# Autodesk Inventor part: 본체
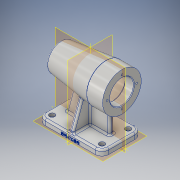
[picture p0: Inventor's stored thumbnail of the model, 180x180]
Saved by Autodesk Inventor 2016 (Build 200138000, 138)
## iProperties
Created: 2018-09
Part Number: 본체
Material: 알루미늄 6061
Document SubType Name: Modeling
Designer: CAMTIC
Density: 2.7 g/cm^3
Appearance: 알루미늄 - 평지
Author: CAMTIC
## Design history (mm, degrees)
sketch "스케치2"
  geometry: L1 (-56, 0)-(56, 0); L2 (56, 0)-(56, 10); L3 (56, 10)-(-56, 10); L4 (-56, 10)-(-56, 0); L5 (0, 12)-(0, -2) reference; L6 (-78.4, 0)-(78.4, 0) reference; L7 (-78.4, 0)-(78.4, 0) reference; L8 (0, -2)-(0, 12) reference; 2 further points
  constraints: 8 end point, 2 parallel, 1 collinear, 1 horizontal, 1 midpoint, 1 perpendicular, 1 point on line
  dimensions: "d0" = 112 distance of L2.end L3.end; "d1" = 10 distance of L1.end L2.end
extrude "돌출1" new body sketch "스케치2" stored distance "d2" = 70; taper "d3" = 0 deg
sketch "스케치3"
  geometry: L1 (56, 84)-(56, 118); L2 (56, 118)-(28, 118); L3 (28, 118)-(-50.331, 108.382); L4 (56, 84)-(-56, 84); L5 (0, 90.525)-(0, -15.088) reference; L6 (-102.597, 0)-(82.433, 0) reference; L7 (-102.597, 0)-(82.433, 0) reference; L8 (0, -15.088)-(0, 90.525) reference; L9 (56, 10)-(-56, 10) reference; A1 r 80 centre (24, 84) between (-52.847, 106.238) and (-56, 84); A2 r 3 centre (-49.965, 105.405) between (-50.331, 108.382) and (-52.847, 106.238); 3 further points
  constraints: 8 end point, 5 point on circle, 3 point on line, 2 centre point, 2 tangent, 1 horizontal, 1 midpoint, 1 perpendicular, 1 vertical
  dimensions: "d5" = 34 distance between parallel lines of L2 L4; "d6" = 28 distance of L1.end L2.end; "d7" = 160 diameter of A1; "d8" = 7 deg angle of L2 L3; "d9" = 112 distance of L1.start L4.end; "d10" = 74 distance between parallel lines of L9 L4; "d43" = 3 radius of A2
revolve "회전1" sketch "스케치3" stored, may be unused: angle "d11" = 90 deg
fillet "모깎기1" dims "d48" = 3
fillet "모깎기2" dims "d49" = 12
sketch "스케치4"
  geometry: L1 (56, 50)-(56, 118) reference; L2 (56, 84)-(-50, 84); L3 (-47, 94.5)-(-47, 99.7); L4 (-46.7, 100)-(-43, 100); L5 (-43, 100)-(-43, 101.2); L6 (-42.7, 101.5)-(-25, 101.5); L7 (-25, 101.5)-(-25, 104.7); L8 (-24.7, 105)-(-13, 105); L9 (-13, 105)-(-13, 105); L10 (-10, 108)-(38, 108); L11 (41, 105)-(41, 105); L12 (41, 105)-(56, 105); L13 (-50, 84)-(-50, 91.5); L14 (-47, 94.5)-(-47, 94.5); L15 (56, 105)-(56, 84); A1 r 0.3 centre (-46.7, 99.7) between (-46.7, 100) and (-47, 99.7); A2 r 0.3 centre (-42.7, 101.2) between (-42.7, 101.5) and (-43, 101.2); A3 r 0.3 centre (-24.7, 104.7) between (-24.7, 105) and (-25, 104.7); A4 r 3 centre (-10, 105) between (-10, 108) and (-13, 105); A5 r 3 centre (38, 105) between (41, 105) and (38, 108); A6 r 3 centre (-47, 91.5) between (-47, 94.5) and (-50, 91.5); 2 further points
  constraints: 28 end point, 12 point on circle, 12 tangent, 10 perpendicular, 6 centre point, 5 point on line, 3 equal radius, 1 collinear, 1 horizontal, 1 midpoint, 1 vertical
  dimensions: "d12" = 15 distance between parallel lines of L1 L11; "d13" = 54 distance between parallel lines of L9 L11; "d14" = 12 distance between parallel lines of L7 L9; "d15" = 18 distance from line of L4.end L7; "d16" = 4 distance between parallel lines of L3 L5; "d17" = 3 distance of L3.start point (-50, 94.5); "d18" = 10.5 distance between parallel lines of L2 L14; "d19" = 16 distance between parallel lines of L2 L4; "d20" = 17.5 distance between parallel lines of L2 L6; "d21" = 21 distance between parallel lines of L2 L8; "d22" = 24 distance between parallel lines of L2 L10; "d23" = 0.3 radius of A1; "d24" = 3 radius of A4; "d25" = 3 radius of A6
revolve "회전2" sketch "스케치4" stored, may be unused: angle "d26" = 90 deg
hole "구멍1" diameter "d52" = 5.5; stored, may be unused: countersink angle "d56" = 90 deg, drill point angle "d58" = 118 deg; dims "d50" = 10, "d51" = 10, "d53" = 6, "d54" = 9.5, "d55" = 5.4, "d57" = 8
hole "구멍2" diameter "d61" = 5.5; stored, may be unused: countersink angle "d65" = 90 deg, drill point angle "d67" = 118 deg; dims "d59" = 10, "d60" = 10, "d62" = 6, "d63" = 9.5, "d64" = 5.4, "d66" = 8
sketch "스케치7"
  geometry: L1 (-49, -84)-(49, -84) reference; L2 (0, -107.6)-(0, 57.6) reference; L3 (0, -107.6)-(0, 57.6) reference; L4 (49, -84)-(-49, -84) reference; C1 r 21 at (0, 0) reference; 2 further points
  constraints: 1 point on line
  dimensions: "d68" = 26 distance of C1.centre point (0, 26)
hole "구멍3" sketch "스케치7" at (0, 26) diameter "d69" = 3.242; stored, may be unused: countersink angle "d73" = 90 deg, drill point angle "d75" = 118 deg; dims "d70" = 8, "d71" = 9.5, "d72" = 5.4, "d74" = 11
chamfer "모따기2" distance "d79" = 1; stored, may be unused: second distance "d80" = 2, angle "d81" = 45 deg
sketch "스케치8"
  geometry: L1 (88, 67)-(0, 67) reference; L2 (100, 55)-(100, 9) reference; L3 (0, -3)-(88, -3) reference; L4 (-12, 55)-(-12, 9) reference; L5 (44, 84.479)-(44, -20.479) reference; L6 (125.879, 32)-(-37.879, 32) reference; L7 (-37.879, 32)-(125.879, 32) reference; L8 (44, 84.479)-(44, -20.479) reference; L9 (6, 36)-(82, 36); L10 (82, 36)-(82, 28); L11 (82, 28)-(6, 28); L12 (6, 28)-(6, 36); L13 (40, 67)-(48, 67); L14 (48, 67)-(48, -3); L15 (48, -3)-(40, -3); L16 (40, -3)-(40, 67); C1 r 2.75 at (0, 9) reference; C2 r 2.75 at (0, 55) reference; C3 r 2.75 at (88, 55) reference; C4 r 2.75 at (88, 9) reference; A1 r 12 centre (0, 55) between (0, 67) and (-12, 55) reference; A2 r 12 centre (88, 55) between (100, 55) and (88, 67) reference; A3 r 12 centre (88, 9) between (88, -3) and (100, 9) reference; A4 r 12 centre (0, 9) between (-12, 9) and (0, -3) reference; 3 further points
  constraints: 16 end point, 4 parallel, 2 collinear, 2 horizontal, 2 midpoint, 2 perpendicular, 2 point on line
  dimensions: "d91" = 18 distance between parallel lines of L4 L12; "d92" = 18 distance between parallel lines of L2 L10; "d93" = 8 distance between parallel lines of L16 L14; "d94" = 8 distance between parallel lines of L11 L9
extrude "돌출4" join sketch "스케치8" distance "d89" = 50; taper "d90" = 0 deg
feature "면 기울기3" dims angle "d95" = 20 deg
feature "면 기울기4" dims angle "d96" = 15 deg
fillet "모깎기3" dims "d97" = 3
fillet "모깎기4" dims "d98" = 3
fillet "모깎기5" dims "d99" = 3
fillet "모깎기6" dims "d100" = 3
fillet "모깎기7" dims "d101" = 3
fillet "모깎기8" dims "d102" = 3
fillet "모깎기9" dims "d103" = 3
fillet "모깎기10" dims "d104" = 3
fillet "모깎기11" dims "d105" = 3
fillet "모깎기12" dims "d106" = 3
fillet "모깎기13" dims "d107" = 3
sketch "스케치9"
  geometry: L1 (-5.899, 4.74)-(5.899, 4.74); L2 (5.899, 4.74)-(5.899, 1.26); L3 (5.899, 1.26)-(-5.899, 1.26); L4 (-5.899, 1.26)-(-5.899, 4.74); L5 (-44, 0)-(44, 0) reference; L6 (56, 0)-(56, 7) reference; 3 further points
  constraints: 2 midpoint, 2 other
  dimensions: "d108" = 3 distance from line of L5 point (5.899, 3); "d110" = 56 distance from line of L6 point (0, 4.74)
feature "엠보싱1" sketch "스케치9" dims "d0" = 112, "d1" = 10, "d111" = 0.5, "d112" = 0
fillet "모깎기14" dims "d113" = 3
node "솔리드1"
mirror "대칭1"
pattern_circular "원형 패턴1" dims angle "d77" = 360 deg
node "투영된 루프1"
other parameters: "d30" = 8, "d31" = 8, "d37" = 8, "d38" = 8
